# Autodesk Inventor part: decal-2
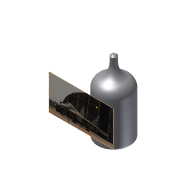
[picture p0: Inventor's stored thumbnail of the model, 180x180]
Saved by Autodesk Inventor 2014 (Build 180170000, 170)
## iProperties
Shininess: 64.0
Length Units: 11269
Angle Units: 11279
Time Units: 11290
Mass Units: 11283
Length Display Precision: 3
Angle Display Precision: 2
Compacted: True
Part Number: decal-2
Document SubType Name: Modeling
Created: 2002-12
Designer: deepak
Material: Generic
Density: 1 g/cm^3
Appearance: Default
Density: 0.0
Volumn: 0.0
Area: 0.0
PropertySet Name: Model Information
Control State: 0
Master: False
Checked Out: False
Author: deepak
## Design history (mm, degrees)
node "Sketch1"
sketch "Sketch2"
  geometry: L1 (2.054, 26.655)-(2.054, 21.177); L2 (11.64, 6.114)-(11.64, -24.209); L3 (11.64, -24.209)-(-0.098, -24.209); L4 (-0.098, -24.209)-(-0.098, 26.655); L5 (-0.098, 26.655)-(2.054, 26.655); A1 r 9.502 centre (11.556, 21.177) between (2.054, 21.177) and (7.532, 12.57); A2 r 7.127 centre (4.514, 6.114) between (11.64, 6.114) and (7.532, 12.57)
  constraints: 10 end point, 4 point on circle, 3 parallel, 3 tangent, 2 centre point, 1 perpendicular, 1 vertical
revolve "Revolution1" sketch "Sketch2" stored, may be unused: angle "d0" = 90 deg
fillet "Fillet1" dims "d1" = 2
chamfer "Chamfer1" distance "d2" = 1; stored, may be unused: second distance "d3" = 2, angle "d21" = 45 deg
workplane "Work Plane4"
sketch "Sketch7"
  geometry: L1 (-11.326, 14.075)-(33.849, 14.075); L2 (33.849, 14.075)-(33.849, -10.781); L3 (33.849, -10.781)-(-11.326, -10.781); L4 (-11.326, -10.781)-(-11.326, 14.075); 1 further point; 1 other entity
  constraints: 2 other
  node "Image6"
body "Solid1"
